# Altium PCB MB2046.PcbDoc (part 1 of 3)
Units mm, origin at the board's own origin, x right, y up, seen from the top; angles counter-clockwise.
Board outline 70 x 82.5 mm, 2 copper layers (Top Layer, Bottom Layer), stack 1.47 mm thick; 179 components, 148 nets, 719 pads, 862 vias.
Unrouted connection lines stored in the file: 135.
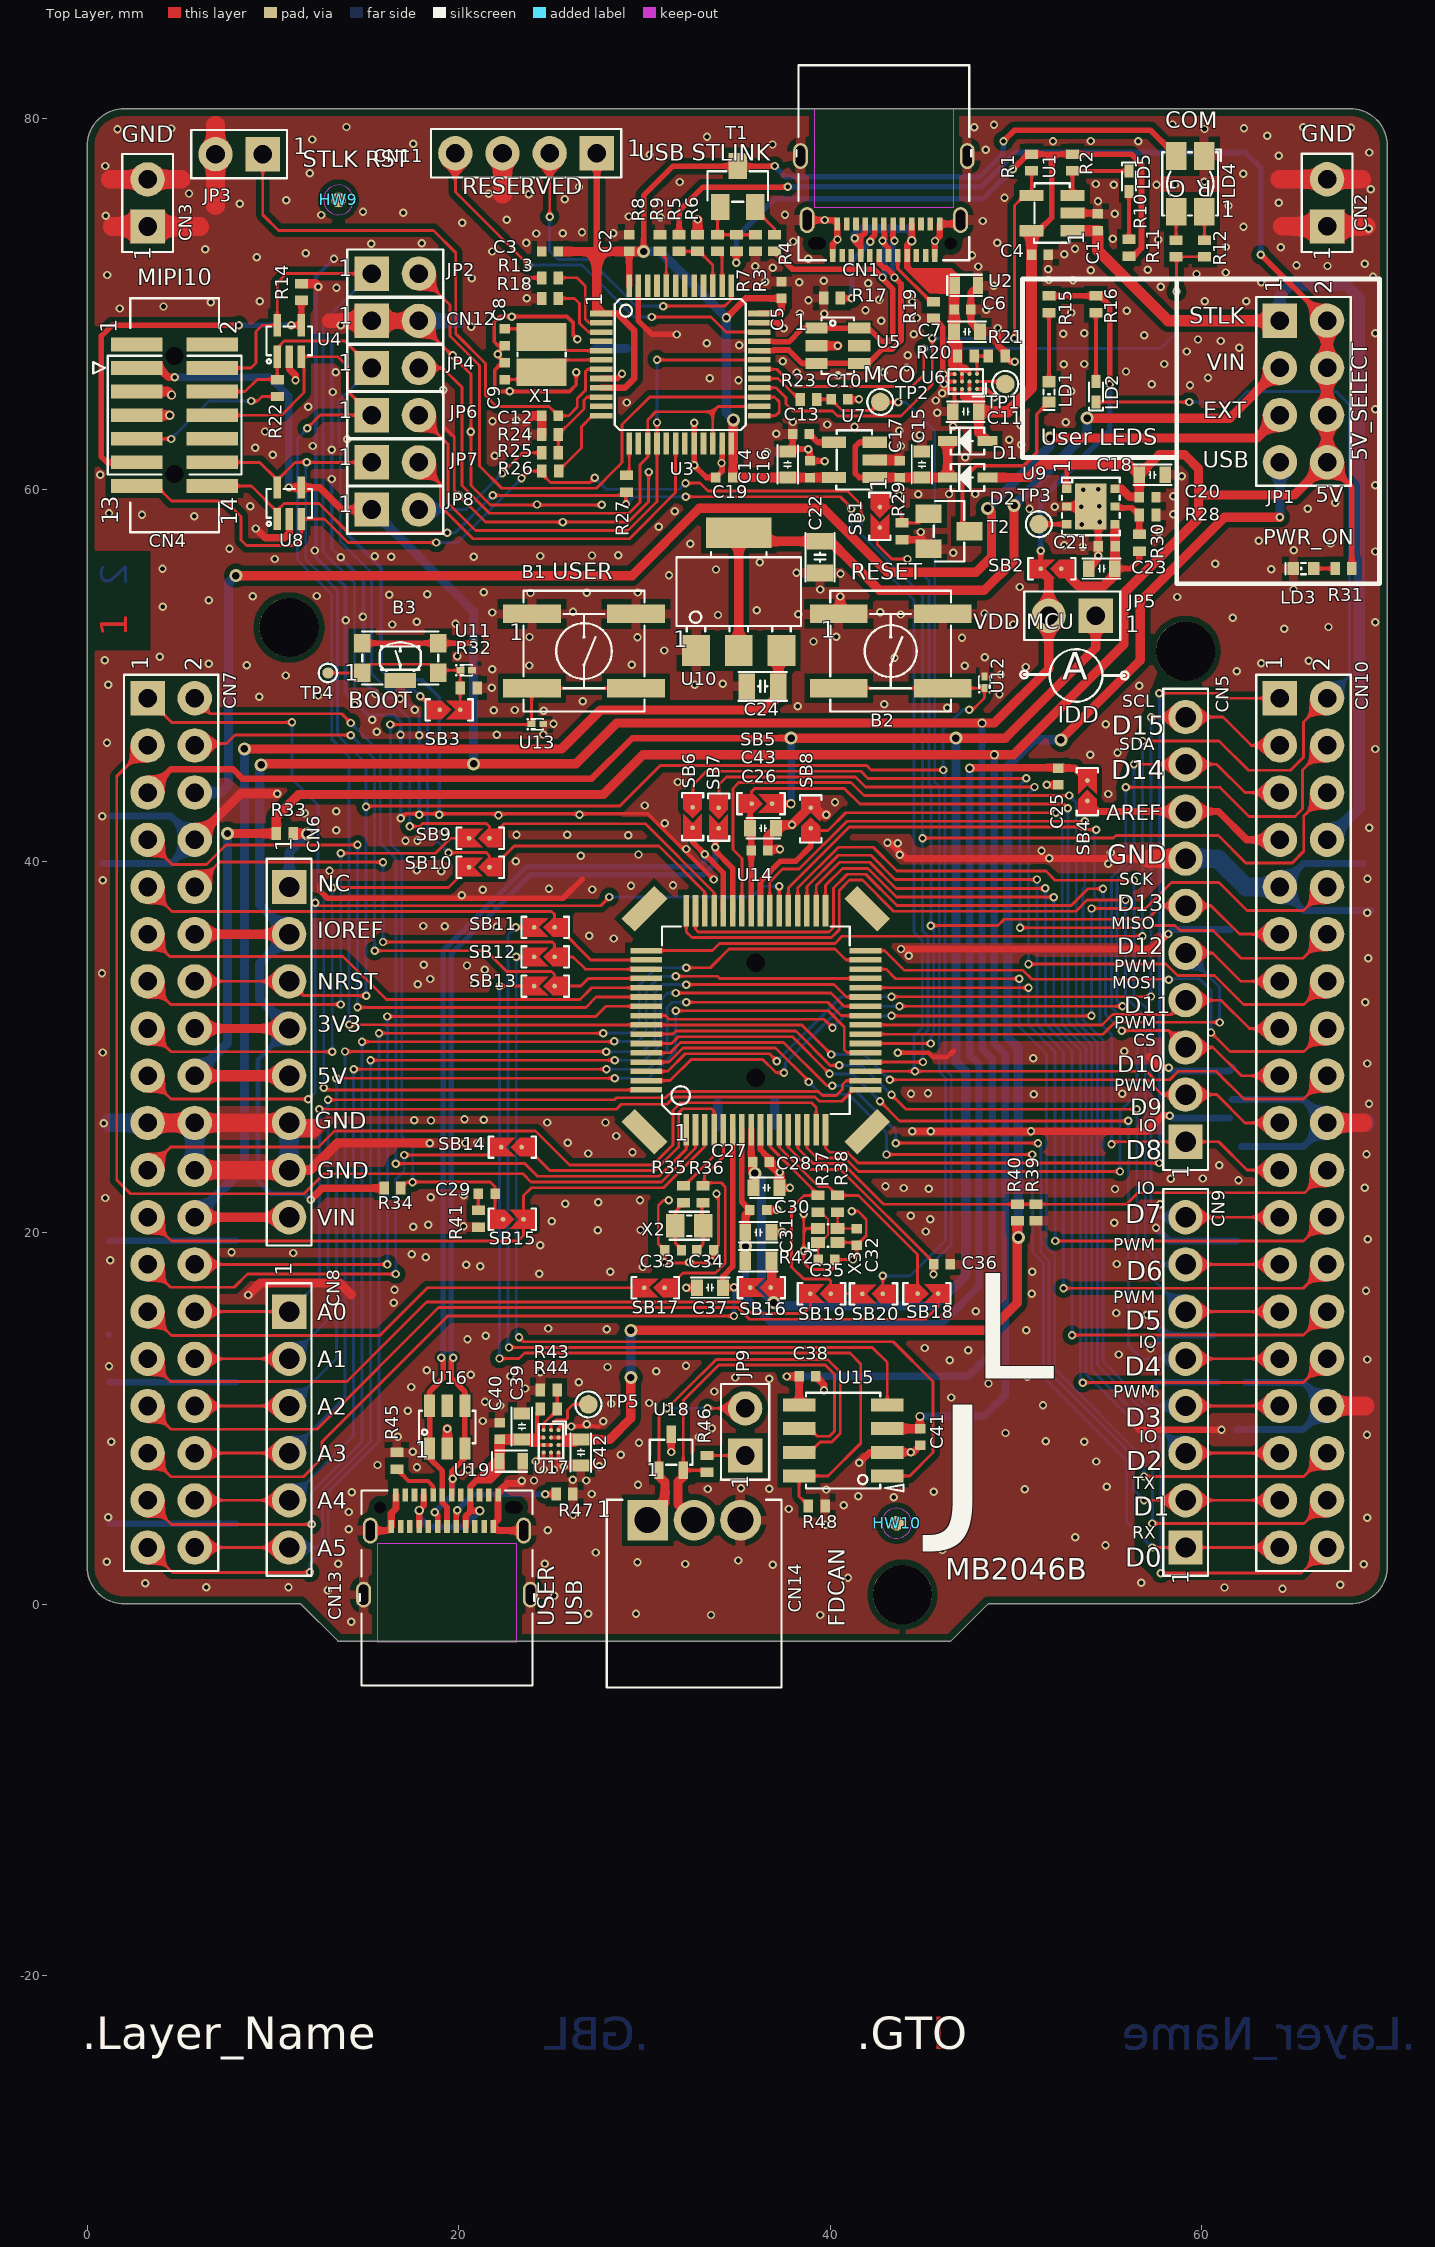
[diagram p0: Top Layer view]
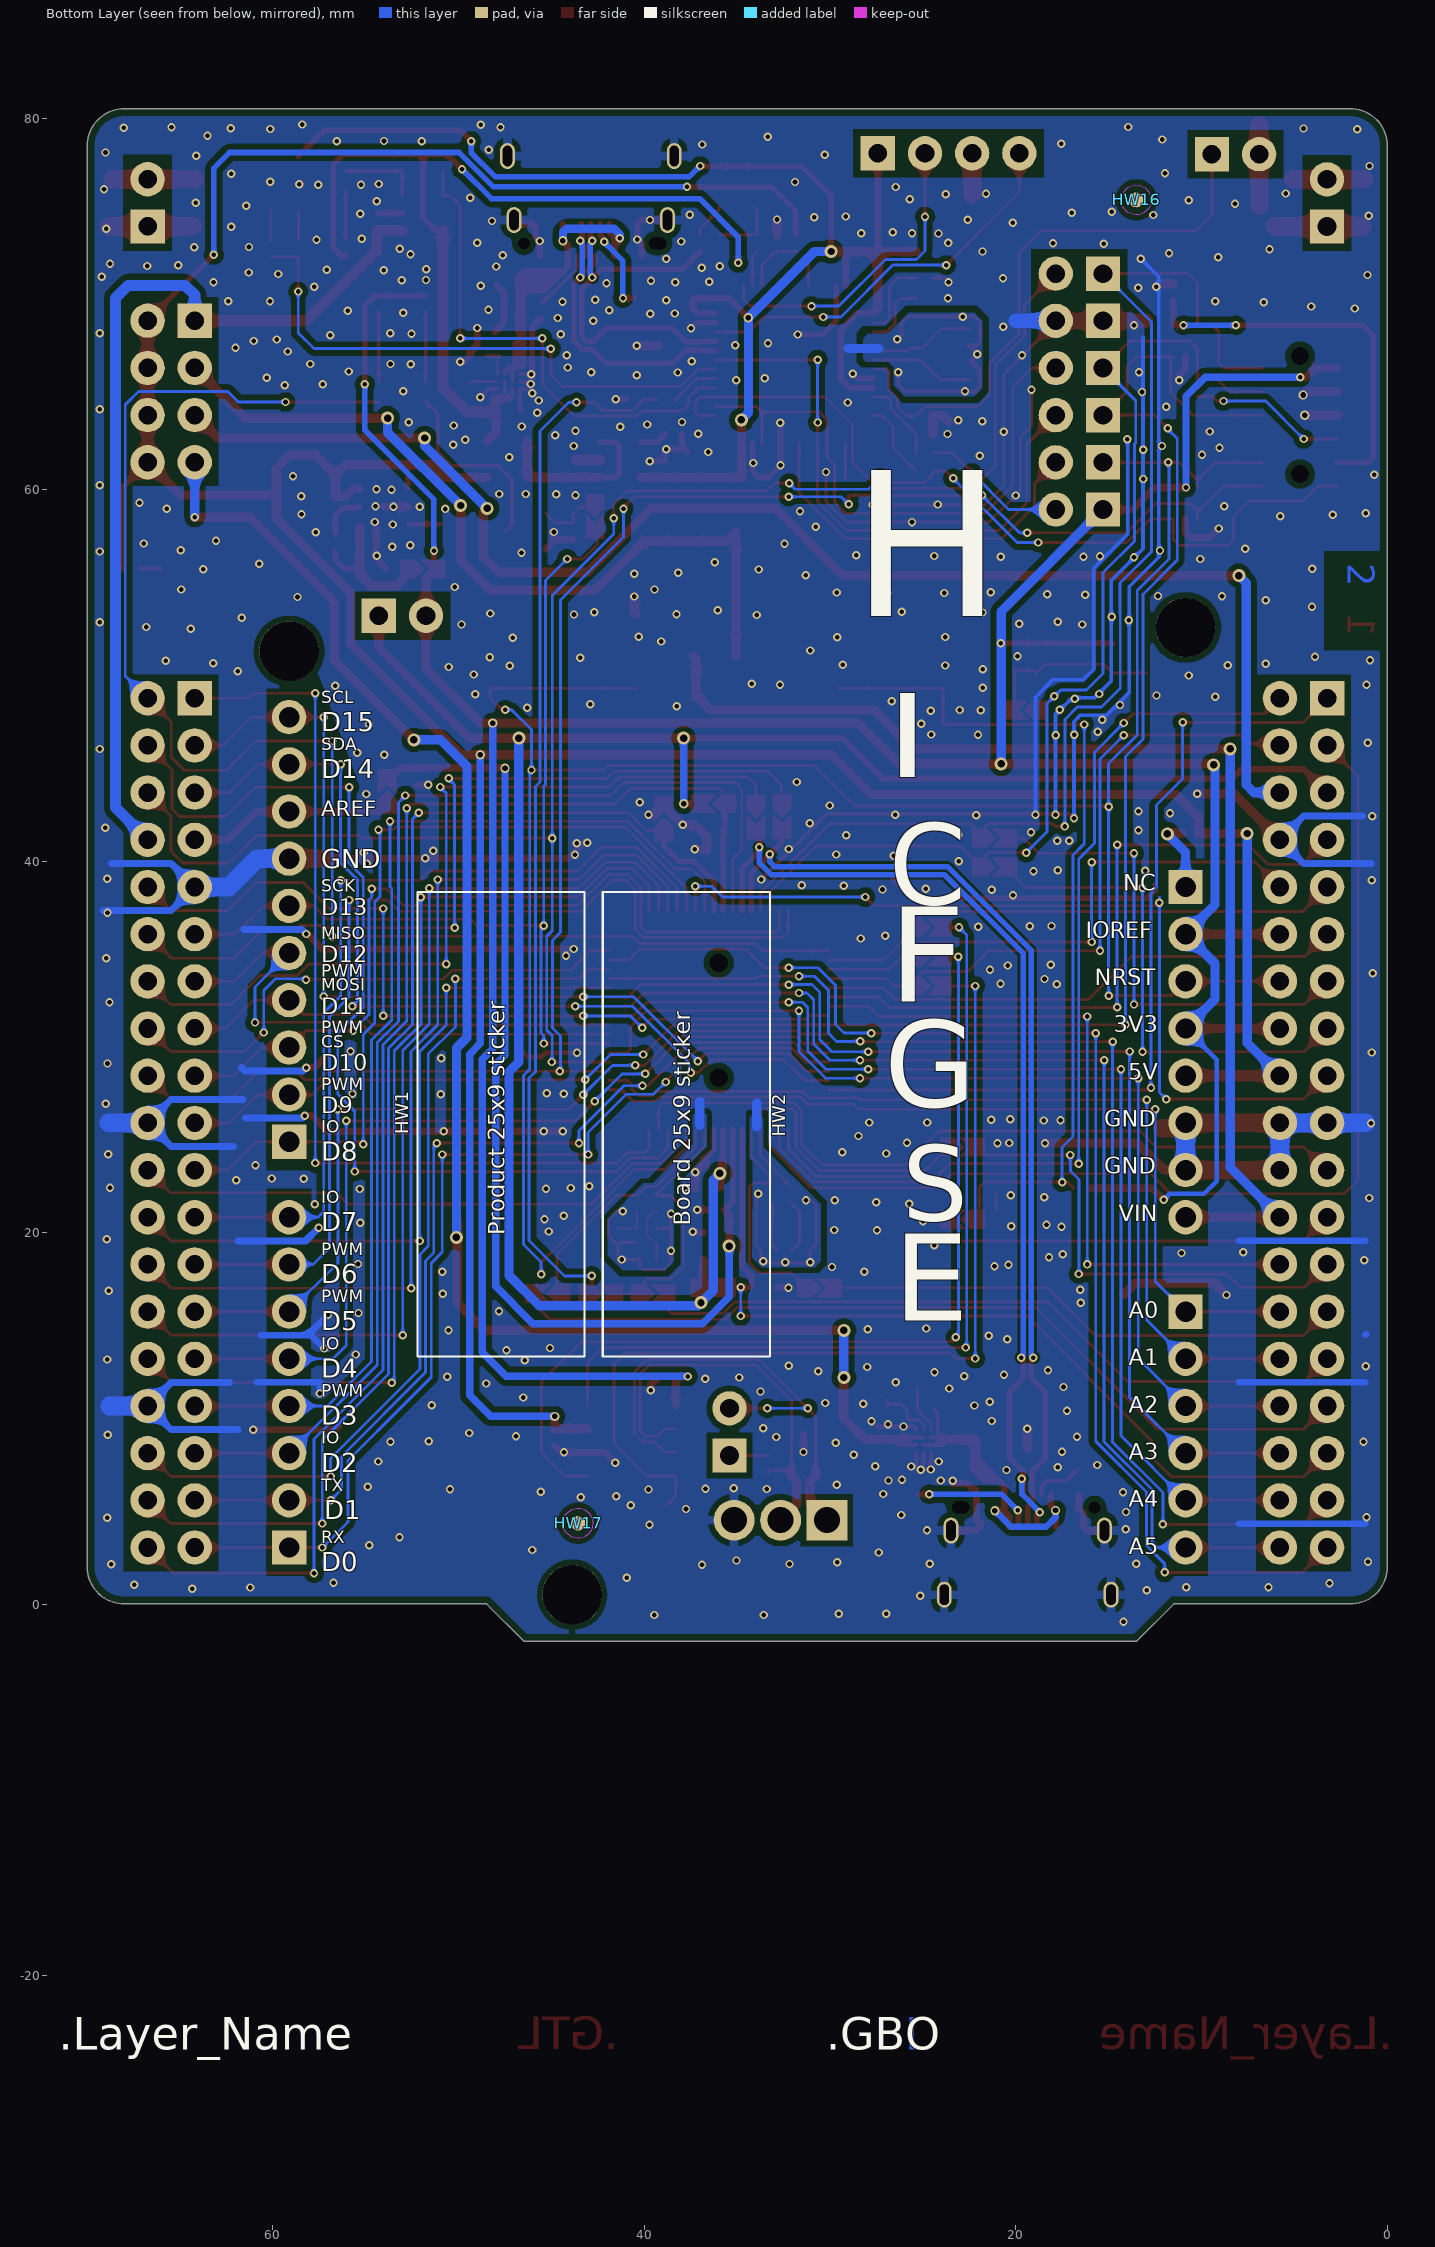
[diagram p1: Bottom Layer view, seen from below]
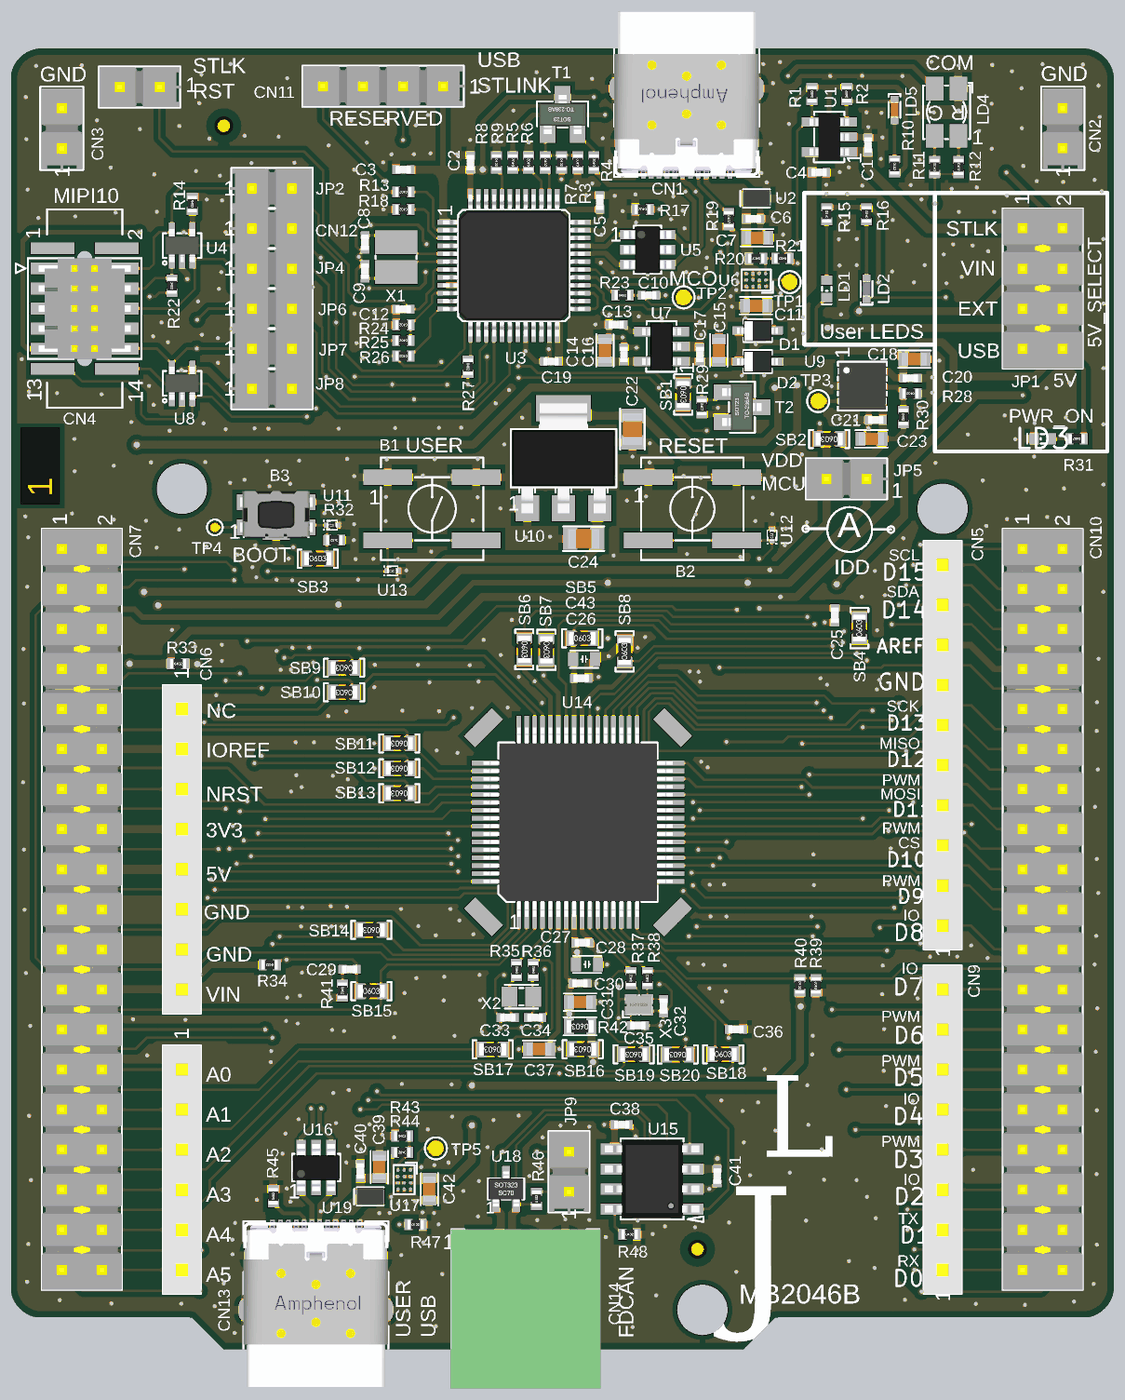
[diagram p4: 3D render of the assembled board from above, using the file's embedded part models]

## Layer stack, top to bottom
Top Solder: solder mask 0.015, Solder Resist, Dk 3.5
Top Layer: signal copper 0.035
Dielectric 1: core 1.4, Dk 4.2
Bottom Layer: signal copper 0.035
Bottom Solder: solder mask 0.015, Solder Resist, Dk 3.5

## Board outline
2.001,0.008 11.501,0.008 13.501,-1.992 46.501,-1.992 48.501,0.008 68.001,0.008 ccw(c68.001,2.008) 70.001,2.008 70.001,78.508 ccw(c68.001,78.508) 68.001,80.508 2.001,80.508 ccw(c2.001,78.508) 0.001,78.508 0.001,2.008 ccw(c2.001,2.008)

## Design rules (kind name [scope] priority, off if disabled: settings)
BoardOutlineClearance [All] p1: gap=0.4 ignorepadtopadclearanceinfootprint=FALSE
Clearance VIA&VIA [IsVia vs IsVia] p1: gap=0.152 ignorepadtopadclearanceinfootprint=TRUE except(0: Arc-Hole Track-Hole SMDPad-Hole THPad-Hole Via-Hole Fill-Hole Poly-Hole Region-Hole Text-Hole; 0.2: Via-Via)
Clearance STLK_USB [InDifferentialPair('STLK_USB')  OR InDifferentialPair('USB.D')] p2: gap=0.134 ignorepadtopadclearanceinfootprint=TRUE
Clearance X3 [(HasFootprint('CRY_NX1612SA_4P'))] p3: gap=0.1 ignorepadtopadclearanceinfootprint=TRUE
Clearance POLOGON [InPolygon] p4: gap=0.3 ignorepadtopadclearanceinfootprint=TRUE except(0: Arc-Hole Track-Hole SMDPad-Hole THPad-Hole Via-Hole Fill-Hole Poly-Hole Region-Hole Text-Hole)
Clearance SB [(HasFootprint('SOLDER-BRIDGE_R0603-0R'))] p5: gap=0.152 ignorepadtopadclearanceinfootprint=TRUE
Clearance [All] p6: gap=0.152 ignorepadtopadclearanceinfootprint=TRUE except(0: Arc-Hole Track-Hole SMDPad-Hole THPad-Hole Via-Hole Fill-Hole Poly-Hole Region-Hole Text-Hole; 0.15: THPad-Fill THPad-Poly THPad-Region; 0.2: SMDPad-SMDPad SMDPad-THPad THPad-THPad THPad-Via Via-Via)
ComponentClearance [All] p1 off: gap=0.025 collisioncheckmode=3 verticalgap=2540 showdistances=TRUE
DiffPairsRouting DiffPairsRouting_USB [InDifferentialPair('STLK_USB')OR InDifferentialPair('USB.D')] p1: maxlimit=0.134 minlimit=0.134 mostfreqgap=0.134 toplayer_minwidth=0.3 toplayer_maxwidth=0.3 toplayer_prefwidth=0.3 bottomlayer_minwidth=0.3 bottomlayer_maxwidth=0.3 bottomlayer_prefwidth=0.3 maxuncoupledlength=50
FanoutControl Fanout_BGA [IsBGA] p1: bgadir=Out bgaviamode=Closest fanoutstyle=Auto fanoutdirection=Alternating viagrid=0.025 // Fanout_BGA (Default Rule)
FanoutControl Fanout_LCC [IsLCC] p2: bgadir=Out bgaviamode=Closest fanoutstyle=Auto fanoutdirection=Alternating viagrid=0.025 // Fanout_LCC (Default Rule)
FanoutControl Fanout_SOIC [IsSOIC] p3: bgadir=Out bgaviamode=Closest fanoutstyle=Auto fanoutdirection=Alternating viagrid=0.025 // Fanout_SOIC (Default Rule)
FanoutControl Fanout_Small [(CompPinCount < 5)] p4: bgadir=Out bgaviamode=Closest fanoutstyle=Auto fanoutdirection=OutThenIn viagrid=0.025 // Fanout_Small (Default Rule)
FanoutControl Fanout_Default [All] p5: bgadir=Out bgaviamode=Closest fanoutstyle=Auto fanoutdirection=Alternating viagrid=0.025 // Fanout_Default (Default Rule)
Height [All] p1 off: minheight=0 maxheight=100 prefheight=0.5
HoleSize [All] p1: absolutevalues=TRUE maxlimit=10 minlimit=0.15 maxpercent=80.000 minpercent=20.000
HoleToHoleClearance [All] p1: gap=0.25 allowstackedmicrovias=TRUE
Length Length_USB [InNetClass('USB')] p1: maxlimit=50 minlimit=1
MatchedLengths [InDifferentialPairClass('DIFF_USB')] p1: tolerance=0.2 checknetsindiffpair=TRUE checkdiffpairvsdiffpair=FALSE checkxsignals=FALSE checkothers=FALSE
MaxMinImpedance "Schematic Impedance Constraint_3" [InNet('STLK_USB_P')] p1: minimum=85.00 maximum=95.00
MaxMinImpedance "Schematic Impedance Constraint_2" [InNet('USB.D_P')] p2: minimum=85.00 maximum=95.00
MaxMinImpedance "Schematic Impedance Constraint_1" [InNet('USB.D_N')] p3: minimum=85.00 maximum=95.00
MaxMinImpedance "Schematic Impedance Constraint" [InNet('STLK_USB_N')] p4: minimum=85.00 maximum=95.00
MinimumSolderMaskSliver [All] p1 off: minsoldermaskwidth=0.1
PlaneClearance [All] p1: clearance=0.6
PolygonConnect VIA [IsVia] p1: connectstyle=Direct reliefconductorwidth=0.254 reliefentries=4 polygonreliefangle="45 Angle" airgapwidth=0.254
PolygonConnect PolygonConnect_1 [All] p2: connectstyle=Relief reliefconductorwidth=0.5 reliefentries=4 polygonreliefangle="90 Angle" airgapwidth=0.3
RoutingVias [All] p1: holewidth=0.25 width=0.45 viastyle="Through Hole" minholewidth=0.25 minwidth=0.45 maxholewidth=0.5 maxwidth=0.7
SilkToSilkClearance [All] p1: silktosilkclearance=0
SilkToSolderMaskClearance [IsPad] p1: minsilkscreentomaskgap=0 clearancetoexposedcopper=TRUE
SolderMaskExpansion [All] p1: expansion=0.05 istentingtop=FALSE
Width Width_ALIM [InNetClass('ALIM')] p1: maxlimit=10 minlimit=0.12 preferedwidth=0.3
Width [All] p2: maxlimit=10 minlimit=0.1 preferedwidth=0.152 minimp=50.000000 maximp=50.000000 favimp=50.000000
16 further rules are at their usual default settings.

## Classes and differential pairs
component class U_TOP: HW9 HW10 HW16 HW17
component class Project_overview: HW1 HW2 HW5
net class PF[0..1]: PF0 PF1
net class PD[0..9]: PD0 PD1 PD2 PD3 PD4 PD5 PD6 PD7 PD8 PD9
component class U_USB-C_Device: C39 C40 C42 CN13 R39 R40 R43 R44 R45 R47 TP5 U16 U17 U19
component class U_FDCAN: C38 C41 CN14 HW15 JP9 R46 R48 U15 U18
component class U_Connectors: C25 CN5 CN6 CN7 CN8 CN9 CN10 R33 SB4 SB9 SB10 SB14 SB17 SB18 SB19
component class U_STM32_microcontroller_IOs: B1 B2 B3 C26 C27 C28 C29 C30 C31 C32 C33 C34 C35 C36 C37 C43 R32 R34 R35 R36 R37 R38 R41 R42 SB3 SB5 SB6 SB7 SB8 SB11 SB12 SB13 SB15 SB16 SB20 TP4 U11 U12 U13 U14 X2 X3
component class Power: C18 C20 C21 C22 C23 C24 CN2 CN3 HW5 HW6 JP1 JP5 LD1 LD2 LD3 R15 R16 R28 R29 R30 R31 SB1 SB2 T2 TP3 U9 U10
component class U_STLINK_V2EC: C1 C2 C3 C4 C5 C6 C7 C8 C9 C10 C11 C12 C13 C14 C15 C16 C17 C19 CN1 CN4 CN11 CN12 D1 D2 HW3 HW4 JP2 JP3 JP4 JP6 JP7 JP8 LD4 LD5 R1 R2 R3 R4 R5 R6 R7 R8 R9 R10 R11 R12 R13 R14 R17 R18 R19 R20 R21 R22 R23 R24 R25 R26 R27 T1 TP1 TP2 U1 U2 U3 U4 U5 U6 U7 U8 X1
net class PA[0..15]: PA0 PA1 PA2 PA3 PA4 PA5 PA6 PA7 PA8 PA9 PA10 PA11 PA12 PA13 PA14 PA15
net class PB[0..15]: PB0 PB1 PB2 PB3 PB4 PB5 PB6 PB7 PB8 PB9 PB10 PB11 PB12 PB13 PB14 PB15
net class PC[0..15]: PC0 PC1 PC2 PC3 PC4 PC5 PC6 PC7 PC8 PC9 PC10 PC11 PC12 PC13 PC14 PC15
differential pair USB.D: +USB.D_P -USB.D_N
differential pair STLK_USB: +STLK_USB_P -STLK_USB_N
differential pair CAN: +CAN_P -CAN_N

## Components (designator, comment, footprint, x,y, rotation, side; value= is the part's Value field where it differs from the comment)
B1 "SW_BLUE_KSC721JLFS" SWI_C&K_KSC721JLFS_BLUE 26.746,51.308 r0 top locked value=KSC721JLFS
B2 "SW_BLACK_KSC321JLFS" SWI_C&K_KSC321JLFS_BLACK 43.256,51.308 r0 top locked value=KSC321JLFS
B3 "SW-PUSH-CMS_KMR2_BLACK" SWI_C&K_Y78B23110FP__ITT_KMR231GLFS 16.855,50.933 r180 top locked value=KMR231GLFS
C1 "Capacitor" C0402 54.407,74.388 r270 top value=100nF
C2 "Capacitor" C0402 29.178,73.27 r90 top value=100nF
C3 "Capacitor" C0402 24.921,72.82 r180 top value=100nF
C4 "Capacitor" C0402 51.293,72.65 r180 top value=100nF
C5 "Capacitor" C0402 37.38,70.747 r90 top value=100nF
C6 "Capacitor" C0402 47.121,69.698 r0 top value=100pF
C7 "Capacitor" C0603 47.371,68.498 r0 top value=100nF
C8 "Capacitor" C0402 22.477,68.206 r90 top value=10pF
C9 "Capacitor" C0402 22.477,66.377 r90 top value=10pF
C10 "Capacitor" C0402 40.496,64.858 r180 top value=20pF
C11 "Capacitor" C0603 47.296,64.195 r0 top value=10uF
C12 "Capacitor" C0402 24.921,63.972 r0 top value=100nF
C13 "Capacitor" C0402 38.429,62.994 r0 top value=10nF
C14 "Capacitor" C0603 37.71,61.35 r270 top value=1uF
C15 "Capacitor" C0603 44.937,61.35 r270 top value=1uF
C16 "Capacitor" C0402 38.911,61.1 r270 top value=100nF
C17 "Capacitor" C0402 43.738,61.1 r270 top value=100nF
C18 "Capacitor" C0603 57.34,60.795 r180 top value=1uF
C19 "Capacitor" C0402 34.292,60.65 r180 top value=100nF
C20 "Capacitor" C0402 57.09,59.592 r180 top value=100nF
C21 "Capacitor" C0402 54.885,56.947 r0 top value=100nF
C22 "Capacitor" C0805 39.45,56.365 r90 top value=10uF
C23 "Capacitor" C0603 54.618,55.748 r0 top value=1uF
C24 "Capacitor" C0805 36.36,49.41 r0 top value=10uF
C25 "Capacitor" C0402 52.285,44.56 r270 top value=100nF
C26 "Capacitor" C0402 36.2,40.57 r180 top value=100nF
C27 "Capacitor" C0402 36.271,23.8 r180 top value=100nF
C28 "Capacitor" C0603_H0P8 36.576,22.416 r180 top value=4.7uF
C29 "Capacitor" C0402 21.508,22.1 r0 top value=100nF
C30 "Capacitor" C0402 36.13,21.216 r180 top value=100nF
C31 "Capacitor" C0603 36.13,20.016 r0 top value=1uF
C32 "Capacitor" C0402 41.424,19.77 r90 top value=6pF
C33 "Capacitor" C0402 31.545,19.05 r0 top value="7.5pF ± 0.1pF"
C34 "Capacitor" C0402 33.274,19.05 r180 top value="7.5pF ± 0.1pF"
C35 "Capacitor" C0402 39.8,18.55 r180 top value=6pF
C36 "Capacitor" C0402 46.025,18.293 r180 top value=100nF
C37 "Capacitor" C0603 33.525,17.043 r180 top value=1uF
C38 "Capacitor" C0402 38.776,12.258 r0 top value=100nF
C39 "Capacitor" C0603 23.4,9.565 r90 top value=100nF
C40 "Capacitor" C0402 22.2,9.315 r90 top value=100pF
C41 "Capacitor" C0402 44.843,8.992 r270 top value=100nF
C42 "Capacitor" C0603 26.575,8.165 r90 top value=10uF
C43 "Capacitor" C0603_H0P8 36.39,41.77 r180 top value=4.7uF
CN1 "USB_TYPE_C_Receptacle" CON_USB-TYPEC_AMPHENOL_12401826E412A 42.89,73.258 r180 top locked value=USB_C_12401826E412A
CN2 "Jumper_Header 2x1" CON_SAMTEC_TSW-102-09-X-S 66.751,75.438 r90 top locked value="Header 2x1"
CN3 "Jumper_Header 2x1" CON_SAMTEC_TSW-102-09-X-S 3.255,75.433 r90 top locked value="Header 2x1"
CN4 "Header 7x2" CON_STDC14_Receiver_MEDIUM_WITH_MIPI10_3D 4.704,64.007 r270 top locked value="Header 5x2"
CN5 "Socket 10x1" CON_SAMTEC_SSW-110-01-X-S 59.131,36.322 r90 top locked
CN6 "Socket 8x1" CON_SAMTEC_SSW-108-01-X-S 10.871,29.718 r270 top locked
CN7 "Header 19x2" CON_SAMTEC_TSW-119-09-X-D 4.521,25.908 r270 top locked
CN8 "Socket 6x1" CON_SAMTEC_SSW-106-01-X-S 10.871,9.398 r270 top locked
CN9 "Socket 8x1" CON_SAMTEC_SSW-108-01-X-S 59.131,11.938 r90 top locked
CN10 "Header 19x2" CON_SAMTEC_TSW-119-09-X-D 65.481,25.908 r270 top locked
CN11 "Header 4x1" CON_SAMTEC_TSW-104-07-G-S 23.63,78.108 r180 top locked
CN12 "Jumper_Header 2x1 Fitted" CON_SAMTEC_TSW-102-07-G-S 16.586,69.088 r0 top locked value="Header 2x1"
CN13 "USB_TYPE_C_Receptacle" CON_USB-TYPEC_AMPHENOL_12401826E412A 19.371,5.208 r0 top locked value=USB_C_12401826E412A
CN14 "Header 3x1" CON_WE-691382010003 32.675,4.518 r0 top locked
D1 "BAT60JFILM" DIO_SOD323 47.395,62.611 r180 top
D2 "BAT60JFILM" DIO_SOD323 47.395,60.65 r180 top
HW1 "STICKER_PRODUCT" STICKER_PRODUCT_25X9 47.727,25.832 r90 bottom locked value=N/A
HW2 "STICKER_BOARD" STICKER_BOARD_25X9 37.744,25.832 r90 bottom locked value=N/A
HW9 "FiducialPad" MIRE_PLACE_SMD_0P8MM 13.527,75.597 r90 top value="Fiducial Pad"
HW10 "FiducialPad" MIRE_PLACE_SMD_0P8MM 43.579,4.355 r90 top value="Fiducial Pad"
HW16 "FiducialPad" MIRE_PLACE_SMD_0P8MM 13.527,75.597 r90 bottom value="Fiducial Pad"
HW17 "FiducialPad" MIRE_PLACE_SMD_0P8MM 43.579,4.355 r90 bottom value="Fiducial Pad"
JP1 "Jumper_Header 4x2 Fitted 1-2" CON_SAMTEC_TSW-104-07-X-D 65.48,65.283 r270 top locked value="Header 4x2"
JP2 "Jumper_Header 2x1 Fitted" CON_SAMTEC_TSW-102-07-G-S 16.586,71.628 r0 top locked value="Header 2x1"
JP3 "Jumper_Header 2x1" CON_SAMTEC_TSW-102-07-G-S 8.18,78.058 r180 top locked value="Header 2x1"
JP4 "Jumper_Header 2x1 Fitted" CON_SAMTEC_TSW-102-07-G-S 16.586,66.548 r0 top locked value="Header 2x1"
JP5 "Jumper_Header 2x1 Fitted" CON_SAMTEC_TSW-102-07-G-S 53.03,53.208 r180 top locked value="Header 2x1"
JP6 "Jumper_Header 2x1 Fitted" CON_SAMTEC_TSW-102-07-G-S 16.586,64.008 r0 top locked value="Header 2x1"
JP7 "Jumper_Header 2x1 Fitted" CON_SAMTEC_TSW-102-07-G-S 16.586,61.468 r0 top locked value="Header 2x1"
JP8 "Jumper_Header 2x1 Fitted" CON_SAMTEC_TSW-102-07-G-S 16.586,58.928 r0 top locked value="Header 2x1"
JP9 "Jumper_Header 2x1" CON_SAMTEC_TSW-102-07-G-S 35.425,9.271 r90 top value="Header 2x1"
LD1 "LED_green" "LED_0402_EVERLIGHT_16-213SYGC/S530-E3-TR8 _YELLOW-GREEN_1A2K_H0P45" 51.78,65.258 r90 top locked value=Yellow/Green
LD2 "LED_blue" LED_0402_KINGBRIGHT_KPHHS-1005QBC-D-V_BLUE_1A2K_H0P5 54.305,65.258 r270 top locked value=Blue
LD3 "LED_green" "LED_0402_EVERLIGHT_16-213SYGC/S530-E3-TR8 _YELLOW-GREEN_1A2K_H0P45" 65.48,55.748 r0 top locked value=Yellow/Green
LD4 "LED_BICOLOR" LED_BI-GR_WE-150141SV73110 59.38,76.458 r180 top locked value=Red/Green
LD5 "LED_red" LED_0402_KINGBRIGHT_KPHHS-1005SURCK_HYPER-RED_1A2K_H0P5 56.083,76.606 r90 top locked value=Red
R1 "Resistor" R0402 50.843,77.606 r90 top value=100K
R2 "Resistor" R0402 53.043,77.606 r90 top value=100K
R3 "Resistor" R0402 35.983,73.271 r90 top value=36K
R4 "Resistor" R0402 37.008,73.271 r90 top value=1K5
R5 "Resistor" R0402 32.863,73.271 r90 top value=10K
R6 "Resistor" R0402 33.934,73.271 r270 top value=100R
R7 "Resistor" R0402 34.959,73.271 r270 top value=10K
R8 "Resistor" R0402 30.828,73.27 r270 top value=100K
R9 "Resistor" R0402 31.863,73.27 r90 top value=5K1
R10 "Resistor" R0402 56.083,73.025 r270 top value=1K
R11 "Resistor" R0402 58.623,72.983 r90 top locked value=330R
R12 "Resistor" R0402 60.147,72.983 r270 top locked value=1K
R13 "Resistor" R0402 24.921,71.403 r180 top value=10K
R14 "Resistor" R0402 11.532,70.637 r270 top value=100R
R15 "Resistor" R0402 51.78,69.983 r90 top value=680R
R16 "Resistor" R0402 54.305,69.983 r90 top value=360R
R17 "Resistor" R0402 40.097,70.303 r180 top value=5K1
R18 "Resistor" R0402 24.921,70.293 r180 top value=10K
R19 "Resistor" R0402 45.564,69.672 r270 top value=5K1
R20 "Resistor" R0402 47.304,67.188 r180 top value=680K
R21 "Resistor" R0402 48.967,67.188 r180 top value=180K
R22 "Resistor" R0402 10.236,65.463 r270 top value=0R
R23 "Resistor" R0402 38.827,64.858 r0 top value=100R
R24 "Resistor" R0402 24.921,62.972 r180 top value=10K
R25 "Resistor" R0402 24.921,61.984 r180 top value=10K
R26 "Resistor" R0402 24.925,60.998 r180 top value=33R
R27 "Resistor" R0402 29.025,60.315 r270 top value=0R
R28 "Resistor" R0402 57.09,58.623 r180 top value=15K
R29 "Resistor" R0402 43.855,57.76 r270 top value=1M
R30 "Resistor" R0402 56.64,57.135 r270 top value=47K
R31 "Resistor" R0402 67.633,55.753 r180 top value=680R
R32 "Resistor" R0402 20.538,49.322 r180 top value=10K
R33 "Resistor" R0402 10.633,41.485 r0 top value=1K
R34 "Resistor" R0402 16.44,22.393 r180 top value=5K1
R35 "Resistor" R0402 32.1,22.065 r90 top value=0R
R36 "Resistor" R0402 33.165,22.065 r90 top value=0R
R37 "Resistor" R0402 39.35,21.552 r90 top value=0R
R38 "Resistor" R0402 40.4,21.552 r90 top value=0R
R39 "Resistor" R0402 51.09,21.085 r90 top value=82K
R40 "Resistor" R0402 50.074,21.085 r270 top value=33K
R41 "Resistor" R0402 21.057,20.75 r270 top value=100R
R42 "Resistor" R0603 36.13,18.489 r180 top value=0R
R43 "Resistor" R0402 24.848,11.533 r0 top value=180K
R44 "Resistor" R0402 24.848,10.492 r180 top value=680K
R45 "Resistor" R0402 16.669,7.714 r90 top value=5K1
R46 "Resistor" R0402 33.368,7.551 r90 top value=120R
R47 "Resistor" R0402 25.698,5.918 r0 top value=5K1
R48 "Resistor" R0402 39.275,5.295 r0 top value=10K
SB1 "SB_ON" SOLDER-BRIDGE_R0603-0R 42.673,58.56 r270 top value=0R
SB2 "SB_ON" SOLDER-BRIDGE_R0603-0R 51.935,55.738 r180 top value=0R
SB3 "SB_ON" SOLDER-BRIDGE_R0603-0R 19.488,48.145 r0 top value=0R
SB4 "SB_ON" SOLDER-BRIDGE_R0603-0R 53.847,43.74 r90 top value=0R
SB5 "SB_ON" SOLDER-BRIDGE_R0603-0R 36.273,43.095 r0 top value=0R
SB6 "SB_ON" SOLDER-BRIDGE_R0603-0R 32.595,42.395 r270 top value=0R
SB7 "SB_ON" SOLDER-BRIDGE_R0603-0R 33.992,42.365 r270 top value=0R
SB8 "SB_ON" SOLDER-BRIDGE_R0603-0R 38.955,42.27 r90 top value=0R
SB9 "SB_ON" SOLDER-BRIDGE_R0603-0R 21.158,41.234 r180 top value=0R
SB10 "SB_ON" SOLDER-BRIDGE_R0603-0R 21.157,39.672 r180 top value=0R
SB11 "SB_ON" SOLDER-BRIDGE_R0603-0R 24.663,36.436 r180 top value=0R
SB12 "SB_ON" SOLDER-BRIDGE_R0603-0R 24.663,34.846 r180 top value=0R
SB13 "SB_ON" SOLDER-BRIDGE_R0603-0R 24.663,33.274 r180 top value=0R
SB14 "SB_ON" SOLDER-BRIDGE_R0603-0R 22.89,24.605 r180 top value=0R
SB15 "SB_ON" SOLDER-BRIDGE_R0603-0R 22.89,20.72 r0 top value=0R
SB16 "SB_ON" SOLDER-BRIDGE_R0603-0R 36.297,17.043 r180 top value=0R
SB17 "SB_ON" SOLDER-BRIDGE_R0603-0R 30.583,17.03 r180 top value=0R
SB18 "SB_ON" SOLDER-BRIDGE_R0603-0R 45.207,16.718 r0 top value=0R
SB19 "SB_ON" SOLDER-BRIDGE_R0603-0R 39.533,16.712 r180 top value=0R
SB20 "SB_ON" SOLDER-BRIDGE_R0603-0R 42.33,16.705 r180 top value=0R
T1 "9013-SOT23" NPN_SOT23 35.027,76.319 r0 top value=BSR14
T2 "BSN20" MOS_SOT23 46.395,57.76 r270 top value=BSN20BK
TP1 "Test Point" TP_SMD_1MM 49.427,65.686 r90 top value=N/A
TP2 "Test Point" TP_SMD_1MM 42.697,64.719 r90 top value=N/A
TP3 "Test Point" TP_SMD_1MM 51.235,58.14 r180 top value=N/A
TP4 "Test Point" TP_SMD_0-6MM 12.96,50.13 r90 top value=N/A
TP5 "Test Point" TP_SMD_1MM 26.982,10.753 r90 top value=N/A
U1 "STMPS2141STR" MOS_SOT23-5L 51.943,74.888 r90 top
U2 "ESD-TRANSIL" ESD_QFN1610_2N_1K_2A 47.326,70.992 r0 top value=ESDA25P35-1U1M
U3 "STLINK-V2EC" ICC_LQFP48_7X7_P050 31.928,66.732 r270 top locked
U4 "ESDALC6V1W5" ESD_SOT323-5L 10.882,68.003 r0 top
U5 "USBLC6-2SC6" ESD_SOT23-6L 40.411,67.742 r270 top
U6 "FPF3380UCX" ICC_WLCSP12_1P858x1P318_P040 47.301,65.818 r180 top
U7 "LDK120M33R" REG_SOT23-5L 41.299,61.6 r90 top
U8 "ESDALC6V1W5" ESD_SOT323-5L 10.882,59.265 r0 top
U9 "LD39100PUR" ICC_DFN6-EPAD_3X3_P095 54.036,59.09 r270 top
U10 "LD1117S50TR" REG_SOT223-TAB 35.077,54.51 r0 top
U11 "ESD-TRANSIL" ESD_ST0201 20.4,50.273 r0 top value=ESDALC6V1-1U2
U12 "ESD-TRANSIL" ESD_ST0201 48.305,49.622 r90 top value=ESDALC6V1-1U2
U13 "ESD-TRANSIL" ESD_ST0201 24.237,47.373 r0 top value=ESDALC6V1-1U2
U14 "STM32C071RB" ICC_LQFP64_10X10_P050_SOCKET_YAMAICHI_IC149-064-069-B5_NM 35.999,31.433 r0 top locked value=STM32C071RBT6
U15 "MCP2562FD" ICC_SO8_5X4_P127 40.701,8.807 r90 top value=MCP2562FDT-H/SN
U16 "USBLC6-2SC6" ESD_SOT23-6L 19.387,9.532 r0 top
U17 "AW329xxFCR" ICC_WLCSP12_1P858x1P318_P040 24.975,8.766 r270 top value=FPF3380UCX
U18 "ESD-TRANSIL-DUAL-BIDIR" DIO_SOT323 31.437,8.179 r0 top value=ESDCAN03-2BWY
U19 "ESD-TRANSIL" ESD_QFN1610_2N_1K_2A 22.825,7.696 r0 top value=ESDA25P35-1U1M
X1 "XTAL_2_PINS" CRY_NX3225GD_2P 24.46,67.266 r90 top value=8MHz
X2 "XTAL_2_PINS" CRY_NX2012SA_2P 32.41,20.369 r180 top value=32.768KHz
X3 "XTAL_4_PINS" CRY_NX1612SA_4P 39.875,19.845 r0 top value=48MHz

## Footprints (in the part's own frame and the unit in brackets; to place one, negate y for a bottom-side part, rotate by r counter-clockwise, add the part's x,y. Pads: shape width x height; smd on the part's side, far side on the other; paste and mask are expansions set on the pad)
C0402 [mm]
  rect 0.51x0.56 smd mask+0.05: 1(-0.45,0) 2(0.45,0)
  body extent -0.5,-0.3 0.5,0.3, height 0.4
C0603 [mm]
  rect 0.64x0.89 smd mask+0.05: 1(-0.7,0) 2(0.7,0)
  silkscreen extent -1.05,-0.55 1.02,0.55, body extent -0.9,-0.5 0.9,0.5, height 1.4
C0603_H0P8 [mm] "MCD-01540"
  rect 0.64x0.89 smd mask+0.05: 1(-0.7,0) 2(0.7,0)
  silkscreen extent -0.9,-0.55 0.9,0.55, body extent -0.9,-0.5 0.9,0.5, height 1
C0805 [mm]
  rect 0.9x1.4 smd mask+0.05: 1(-0.85,0) 2(0.85,0)
  silkscreen extent -1.3,-0.77 1.3,0.77, body extent -1.1,-0.7 1.1,0.7, height 1.35
CON_SAMTEC_SSW-106-01-X-S [mm] "MCD-02079"
  rect 1.85x1.85 / inner round 1.85 / far side rect 1.85x1.85 hole 1.1 mask+0.05: 1(-6.35,0)
  round 1.85 hole 1.1 mask+0.05: 2(-3.81,0) 3(-1.27,0) 4(1.27,0) 5(3.81,0) 6(6.35,0)
  silkscreen extent -7.88,-1.2 7.88,1.2, body extent -7.88,-1.21 7.88,1.21, height 8.51
CON_SAMTEC_SSW-108-01-X-S [mm] "MCD-01743"
  rect 1.85x1.85 / inner round 1.85 / far side rect 1.85x1.85 hole 1.1 mask+0.05: 1(-8.89,0)
  round 1.85 hole 1.1 mask+0.05: 2(-6.35,0) 3(-3.81,0) 4(-1.27,0) 5(1.27,0) 6(3.81,0) 7(6.35,0) 8(8.89,0)
  silkscreen extent -10.42,-1.2 10.42,1.2, body extent -10.42,-1.21 10.42,1.21, height 8.51
CON_SAMTEC_SSW-110-01-X-S [mm] "MCD-02080"
  rect 1.85x1.85 / inner round 1.85 / far side rect 1.85x1.85 hole 1.1 mask+0.05: 1(-11.43,0)
  round 1.85 hole 1.1 mask+0.05: 2(-8.89,0) 3(-6.35,0) 4(-3.81,0) 5(-1.27,0) 6(1.27,0) 7(3.81,0) 8(6.35,0) 9(8.89,0) 10(11.43,0)
  silkscreen extent -12.96,-1.2 12.96,1.2, body extent -12.96,-1.21 12.96,1.21, height 8.51
CON_SAMTEC_TSW-102-07-G-S [mm]
  rect 1.85x1.85 / inner round 1.85 / far side rect 1.85x1.85 hole 1 mask+0.05: 1(-1.27,0)
  round 1.85 hole 1 mask+0.05: 2(1.27,0)
  silkscreen extent -2.58,-1.3 2.58,1.3, body extent -2.67,-1.3 2.58,1.3, height 8.38
CON_SAMTEC_TSW-102-09-X-S [mm]
  rect 1.85x1.85 / inner round 1.85 / far side rect 1.85x1.85 hole 1 mask+0.05: 1(-1.27,0)
  round 1.85 hole 1 mask+0.05: 2(1.27,0)
  silkscreen extent -2.64,-1.37 2.64,1.37, body extent -2.67,-1.3 2.58,1.3, height 8.38
CON_SAMTEC_TSW-104-07-G-S [mm]
  rect 1.85x1.85 / inner round 1.85 / far side rect 1.85x1.85 hole 1 mask+0.05: 1(-3.81,0)
  round 1.85 hole 1 mask+0.05: 2(-1.27,0) 3(1.27,0) 4(3.81,0)
  silkscreen extent -5.12,-1.3 5.12,1.3, body extent -5.21,-1.37 5.18,1.37, height 8.38
CON_SAMTEC_TSW-104-07-X-D [mm]
  rect 1.85x1.85 / inner round 1.85 / far side rect 1.85x1.85 hole 1 mask+0.05: 1(-3.81,-1.27)
  round 1.85 hole 1 mask+0.05: 2(-3.81,1.27) 3(-1.27,-1.27) 4(-1.27,1.27) 5(1.27,-1.27) 6(1.27,1.27) 7(3.81,-1.27) 8(3.81,1.27)
  silkscreen extent -5.08,-2.54 5.08,2.54, body extent -5.08,-2.54 5.08,2.54, height 8.38
CON_SAMTEC_TSW-119-09-X-D [mm]
  rect 1.85x1.85 / inner round 1.85 / far side rect 1.85x1.85 hole 1 mask+0.05: 1(-22.86,-1.27)
  round 1.85 hole 1 mask+0.05: 2(-22.86,1.27) 3(-20.32,-1.27) 4(-20.32,1.27) 5(-17.78,-1.27) 6(-17.78,1.27) 7(-15.24,-1.27) 8(-15.24,1.27) 9(-12.7,-1.27) 10(-12.7,1.27) 11(-10.16,-1.27) 12(-10.16,1.27) 13(-7.62,-1.27) 14(-7.62,1.27) 15(-5.08,-1.27) 16(-5.08,1.27) 17(-2.54,-1.27) 18(-2.54,1.27) 19(0,-1.27) 20(0,1.27) 21(2.54,-1.27) 22(2.54,1.27) 23(5.08,-1.27) 24(5.08,1.27) 25(7.62,-1.27) 26(7.62,1.27) 27(10.16,-1.27) 28(10.16,1.27) 29(12.7,-1.27) 30(12.7,1.27) 31(15.24,-1.27) 32(15.24,1.27) 33(17.78,-1.27) 34(17.78,1.27) 35(20.32,-1.27) 36(20.32,1.27) 37(22.86,-1.27) 38(22.86,1.27)
  silkscreen extent -24.13,-2.54 24.13,2.54, body extent -24.13,-2.55 24.13,2.54, height 8.38
CON_STDC14_Receiver_MEDIUM_WITH_MIPI10_3D [mm] "compatible with FTSH-105-01-L-DV,-K and FTSH-107-01-L-DV,-K,-A,-P,-ES"
  round 0 all layers, no hole mask+0: 0(-5.445,0) 0(5.445,0)
  round 0 hole 0.97 unplated mask+0.038: 0(-3.175,0) 0(3.175,0)
  rect 0.74x2.79 smd mask+0.05: 1(-3.81,-2.032) 2(-3.81,2.032) 3(-2.54,-2.032) 4(-2.54,2.032) 5(-1.27,-2.032) 6(-1.27,2.032) 7(0,-2.032) 8(0,2.032) 9(1.27,-2.032) 10(1.27,2.032) 11(2.54,-2.032) 12(2.54,2.032) 13(3.81,-2.032) 14(3.81,2.032)
  silkscreen extent -6.3,-4.38 6.3,3.6, body extent -6.3,-2.92 6.3,2.92, height 6.6
CON_USB-TYPEC_AMPHENOL_12401826E412A [mm] "MCD-03232"
  round 0 hole 0.65 unplated mask+0.05: 0(-3.6,0)
  round 0 hole 0.65 slot 0.95 at 0 deg unplated mask+0.05: 0(3.6,0)
  rect 0.3x0.7 smd mask+0.05: A1(-2.75,0.66) A2(-2.25,0.66) A3(-1.75,0.66) A4(-1.25,0.66) A5(-0.75,0.66) A6(-0.25,0.66) A7(0.25,0.66) A8(0.75,0.66) A9(1.25,0.66) A10(1.75,0.66) A11(2.25,0.66) A12(2.75,0.66) B1(2.5,-1.04) B2(2,-1.04) B3(1.5,-1.04) B4(1,-1.04) B5(0.5,-1.04) B6(0,-1.04) B7(-0.5,-1.04) B8(-1,-1.04) B9(-1.5,-1.04) B10(-2,-1.04) B11(-2.5,-1.04) B12(-3,-1.04)
  oval 0.8x1.4 hole 0.5 slot 1.1 at 90 deg mask+0.05: SH1(-4.13,-1.25) SH2(4.13,-1.25) SH3(-4.49,-4.7) SH4(4.49,-4.7)
  Top Layer keep-out region: -3.75,-7.24 3.75,-7.24 3.75,-1.95 -3.75,-1.95
  silkscreen extent -4.7,-9.59 4.7,0.91, body extent -4.6,-9.59 4.6,0.91, height 3.26
CON_WE-691382010003 [mm]
  rect 2.2x2.2 hole 1.4 mask+0.05: 1(-2.5,0)
  round 2.2 hole 1.4 mask+0.05: 2(0,0) 3(2.5,0)
  silkscreen extent -4.7,-9 4.7,1.1, body extent -4.75,-9 4.75,1.1, height 8.15
CRY_NX1612SA_4P [mm] "MCD-02262"
  rect 0.75x0.6 smd mask+0.038: 1(-0.525,-0.375) 2(0.525,-0.375) 3(0.525,0.375) 4(-0.525,0.375)
  silkscreen extent -1.02,-0.8 0.03,0.6, body extent -0.8,-0.6 0.8,0.6, height 0.51
CRY_NX2012SA_2P [mm]
  rect 1x1.25 smd mask+0.05: 1(-0.75,0) 2(0.75,0)
  silkscreen extent -1.05,-0.75 1.05,0.75, body extent -1.05,-0.63 1.05,0.63, height 0.6
CRY_NX3225GD_2P [mm]
  rect 1.5x2.7 smd mask+0.05: 1(-0.95,0) 2(0.95,0)
  silkscreen extent -0.1,-1.3 0.1,1.3, body extent -1.65,-1.31 1.65,1.3, height 1
DIO_SOD323 [mm]
  rect 1.06x0.54 smd mask+0.05: 1(-1.07,0) 2(1.07,0)
  silkscreen extent -0.9,-0.73 0.9,0.73, body extent -1.3,-0.78 1.3,0.78, height 1.17
DIO_SOT323 [mm]
  rect 0.5x0.95 smd mask+0.05: 1(-0.65,-0.975) 2(0.65,-0.975) 3(0,0.975)
  silkscreen extent -1.15,-0.67 1.15,0.67, body extent -1.15,-1.12 1.15,1.12, height 1.1
ESD_QFN1610_2N_1K_2A [mm] "DFN, 2-Leads, Body 1.60x1.00mm"
  rect 0.55x0.9 smd mask+0.05: 1(-0.625,0) 2(0.625,0)
  silkscreen extent -1.02,-0.58 0.85,0.58, body extent -0.85,-0.55 0.85,0.55, height 0.6
ESD_SOT23-6L [mm]
  rect 0.6x1.2 smd mask+0.05: 1(-0.95,-1.15) 2(0,-1.15) 3(0.95,-1.15) 4(0.95,1.15) 5(0,1.15) 6(-0.95,1.15)
  silkscreen extent -1.53,-0.87 1.53,0.87, body extent -1.52,-1.5 1.52,1.5, height 1.45
ESD_SOT323-5L [mm]
  rect 0.4x1.2 smd mask+0.05: 1(-0.65,-0.85) 2(0,-0.85) 3(0.65,-0.85) 4(0.65,0.85) 5(-0.65,0.85)
  silkscreen extent -1.23,-1.21 1.23,0.77, body extent -1.15,-1.05 1.15,1.05, height 1.1
ESD_ST0201 [mm]
  rect 0.425x0.33 smd mask+0.05: 1(-0.312,0) 2(0.312,0)
  silkscreen extent -0.55,-0.3 0.33,0.3, body extent -0.34,-0.18 0.34,0.18, height 0.34
ICC_DFN6-EPAD_3X3_P095 [mm]
  rect 0.45x0.5 smd mask+0.05: 1(-0.95,-1.3) 2(0,-1.3) 3(0.95,-1.3) 4(0.95,1.3) 5(0,1.3) 6(-0.95,1.3)
  rect 2.5x1.7 smd mask+0.05: EP(0,0)
  silkscreen extent -1.55,-1.55 1.55,1.55, body extent -1.55,-1.55 1.55,1.55, height 1
ICC_LQFP48_7X7_P050 [mm]
  rect 0.3x1.2 smd mask+0.05: 1(-2.75,-4.25) 2(-2.25,-4.25) 3(-1.75,-4.25) 4(-1.25,-4.25) 5(-0.75,-4.25) 6(-0.25,-4.25) 7(0.25,-4.25) 8(0.75,-4.25) 9(1.25,-4.25) 10(1.75,-4.25) 11(2.25,-4.25) 12(2.75,-4.25) 25(2.75,4.25) 26(2.25,4.25) 27(1.75,4.25) 28(1.25,4.25) 29(0.75,4.25) 30(0.25,4.25) 31(-0.25,4.25) 32(-0.75,4.25) 33(-1.25,4.25) 34(-1.75,4.25) 35(-2.25,4.25) 36(-2.75,4.25)
  rect 1.2x0.3 smd mask+0.05: 13(4.25,-2.75) 14(4.25,-2.25) 15(4.25,-1.75) 16(4.25,-1.25) 17(4.25,-0.75) 18(4.25,-0.25) 19(4.25,0.25) 20(4.25,0.75) 21(4.25,1.25) 22(4.25,1.75) 23(4.25,2.25) 24(4.25,2.75) 37(-4.25,2.75) 38(-4.25,2.25) 39(-4.25,1.75) 40(-4.25,1.25) 41(-4.25,0.75) 42(-4.25,0.25) 43(-4.25,-0.25) 44(-4.25,-0.75) 45(-4.25,-1.25) 46(-4.25,-1.75) 47(-4.25,-2.25) 48(-4.25,-2.75)
  silkscreen extent -3.52,-3.52 3.53,3.52, body extent -4.5,-4.5 4.5,4.5, height 1.6
ICC_LQFP64_10X10_P050_SOCKET_YAMAICHI_IC149-064-069-B5_NM [mm]
  rect 1x2.5 smd rot 45 mask+0.05: 0(-6,-6) 0(6,6)
  rect 1x2.5 smd rot 135 mask+0.05: 0(-6,6) 0(6,-6)
  round 0.5 hole 1 unplated mask+0.05: 0(0,-3.1) 0(0,3.1)
  rect 0.3x1.7 smd mask+0.05: 1(-3.75,-5.9) 2(-3.25,-5.9) 3(-2.75,-5.9) 4(-2.25,-5.9) 5(-1.75,-5.9) 6(-1.25,-5.9) 7(-0.75,-5.9) 8(-0.25,-5.9) 9(0.25,-5.9) 10(0.75,-5.9) 11(1.25,-5.9) 12(1.75,-5.9) 13(2.25,-5.9) 14(2.75,-5.9) 15(3.25,-5.9) 16(3.75,-5.9) 33(3.75,5.9) 34(3.25,5.9) 35(2.75,5.9) 36(2.25,5.9) 37(1.75,5.9) 38(1.25,5.9) 39(0.75,5.9) 40(0.25,5.9) 41(-0.25,5.9) 42(-0.75,5.9) 43(-1.25,5.9) 44(-1.75,5.9) 45(-2.25,5.9) 46(-2.75,5.9) 47(-3.25,5.9) 48(-3.75,5.9)
  rect 1.7x0.3 smd mask+0.05: 17(5.9,-3.75) 18(5.9,-3.25) 19(5.9,-2.75) 20(5.9,-2.25) 21(5.9,-1.75) 22(5.9,-1.25) 23(5.9,-0.75) 24(5.9,-0.25) 25(5.9,0.25) 26(5.9,0.75) 27(5.9,1.25) 28(5.9,1.75) 29(5.9,2.25) 30(5.9,2.75) 31(5.9,3.25) 32(5.9,3.75) 49(-5.9,3.75) 50(-5.9,3.25) 51(-5.9,2.75) 52(-5.9,2.25) 53(-5.9,1.75) 54(-5.9,1.25) 55(-5.9,0.75) 56(-5.9,0.25) 57(-5.9,-0.25) 58(-5.9,-0.75) 59(-5.9,-1.25) 60(-5.9,-1.75) 61(-5.9,-2.25) 62(-5.9,-2.75) 63(-5.9,-3.25) 64(-5.9,-3.75)
  silkscreen extent -5.05,-5.05 5.05,5.05, body extent -6,-6 6,6, height 1.6
ICC_SO8_5X4_P127 [mm]
  rect 0.7x1.75 smd mask+0.05: 1(-1.905,-2.375) 2(-0.635,-2.375) 3(0.635,-2.375) 4(1.905,-2.375) 5(1.905,2.375) 6(0.635,2.375) 7(-0.635,2.375) 8(-1.905,2.375)
  silkscreen extent -2.72,-3.25 2.57,2, body extent -2.57,-3 2.57,3, height 1.75
ICC_WLCSP12_1P858x1P318_P040 [mm] "MCD-03166"
  round 0.215 smd paste+0 mask+0.04: A1(-0.6,0.4) A2(-0.2,0.4) A3(0.2,0.4) A4(0.6,0.4) B1(-0.6,0) B2(-0.2,0) B3(0.2,0) B4(0.6,0) C1(-0.6,-0.4) C2(-0.2,-0.4) C3(0.2,-0.4) C4(0.6,-0.4)
  silkscreen extent -1.07,-0.66 0.93,0.8, body extent -0.93,-0.66 0.93,0.66, height 0.62
"LED_0402_EVERLIGHT_16-213SYGC/S530-E3-TR8 _YELLOW-GREEN_1A2K_H0P45" [mm] "MCD-02330"
  rect 0.6x0.7 smd mask+0.05: 1(0.55,0) 2(-0.55,0)
  silkscreen extent -0.97,-0.3 0.13,0.3, body extent -0.55,-0.3 0.55,0.3, height 0.55
LED_0402_KINGBRIGHT_KPHHS-1005QBC-D-V_BLUE_1A2K_H0P5 [mm] "MCD-00706"
  rect 0.7x0.5 smd mask+0.05: 1(-0.55,0) 2(0.55,0)
  silkscreen extent -0.5,-0.38 1,0.38, body extent -0.5,-0.3 0.51,0.3, height 0.6
LED_0402_KINGBRIGHT_KPHHS-1005SURCK_HYPER-RED_1A2K_H0P5 [mm] "MCD-00708"
  rect 0.7x0.5 smd mask+0.05: 1(-0.55,0) 2(0.55,0)
  silkscreen extent -0.5,-0.38 1,0.38, body extent -0.5,-0.3 0.51,0.3, height 0.6
LED_BI-GR_WE-150141SV73110 [mm] "MCD-02631"
  rect 1.1x1.5 smd mask+0.05: 1(-0.75,1.5) 2(0.75,1.5) 3(-0.75,-1.5) 4(0.75,-1.5)
  silkscreen extent -1.65,-1.85 1.5,1.7, body extent -1.5,-1.85 1.5,1.85, height 2.1
MIRE_PLACE_SMD_0P8MM [mm]
  round 0.8 smd paste-10 mask+0.2: 1(0,0)
  Top Layer keep-out circle w0.01: c0,0 r0.804
MOS_SOT23 [mm]
  rect 1x1.4 smd mask+0.05: 1(-0.95,-1.1) 2(0.95,-1.1) 3(0,1.1)
  silkscreen extent -1.63,-0.82 1.63,0.82, body extent -1.56,-1.25 1.56,1.25, height 1.1
MOS_SOT23-5L [mm]
  rect 0.6x1.3 smd mask+0.05: 1(-0.95,-1.1) 2(0,-1.1) 3(0.95,-1.1) 4(0.95,1.1) 5(-0.95,1.1)
  silkscreen extent -1.6,-0.95 1.6,0.97, body extent -1.52,-1.25 1.52,1.25, height 1.45
NPN_SOT23 [mm]
  rect 1x1.4 smd mask+0.05: 1(-0.95,-1.1) 2(0.95,-1.1) 3(0,1.1)
  silkscreen extent -1.63,-0.82 1.63,0.82, body extent -1.56,-1.25 1.56,1.25, height 1.1
R0402 [mm]
  rect 0.51x0.7 smd mask+0.05: 1(-0.45,0) 2(0.45,0)
  body extent -0.52,-0.3 0.52,0.3, height 0.4
R0603 [mm]
  rect 0.64x1 smd mask+0.05: 1(-0.7,0) 2(0.7,0)
  silkscreen extent -1.05,-0.58 1.05,0.58, body extent -0.9,-0.5 0.9,0.5, height 0.56
REG_SOT23-5L [mm]
  rect 0.6x1.3 smd mask+0.05: 1(-0.95,-1.1) 2(0,-1.1) 3(0.95,-1.1) 4(0.95,1.1) 5(-0.95,1.1)
  silkscreen extent -1.6,-0.95 1.6,0.97, body extent -1.52,-1.25 1.52,1.25, height 1.1
REG_SOT223-TAB [mm]
  rect 1.5x1.65 smd mask+0.05: 1(-2.3,-3.175) 2(0,-3.175) 3(2.3,-3.175)
  rect 3.5x1.65 smd mask+0.05: 4(0,3.175)
  silkscreen extent -3.35,-2.15 3.35,2.12, body extent -3.35,-3.48 3.35,3.48, height 1.8
SOLDER-BRIDGE_R0603-0R [mil]
  round 10 smd paste-393.7: 1(-19.68,0) 2(23.62,0)
  Top Layer region: -5.91,19.68 13.78,0 -5.91,-19.69 47.24,-19.69 47.24,19.68 -5.91,19.68
  Top Layer region: -47.24,-19.69 -47.24,19.68 -15.75,19.68 3.94,0 -15.75,-19.69 -47.24,-19.69
  silkscreen extent -50,-23 50,23, body extent -36,-20 36,20, height 22
STICKER_BOARD_25X9 [mm] "Sticker to mention board CPN code"
  silkscreen extent -12.5,-4.5 12.5,4.5
STICKER_PRODUCT_25X9 [mm] "Sticker to mention board CPN code"
  silkscreen extent -12.5,-4.5 12.5,4.5
SWI_C&K_KSC321JLFS_BLACK [mm] "MCD-01799"
  rect 3.1x1 smd mask+0.05: 1(-2.8,2) 2(2.8,2) 3(-2.8,-2) 4(2.8,-2)
  silkscreen extent -3.25,-3.25 3.25,3.25, body extent -3.4,-3.25 3.4,3.25, height 3.5
SWI_C&K_KSC721JLFS_BLUE [mm] "MCD-01800"
  rect 3.1x1 smd mask+0.05: 1(-2.8,2) 2(2.8,2) 3(-2.8,-2) 4(2.8,-2)
  silkscreen extent -3.25,-3.25 3.25,3.25, body extent -3.4,-3.25 3.4,3.25, height 4.3
SWI_C&K_Y78B23110FP__ITT_KMR231GLFS [mm] "MCD-00715"
  rect 0.9x1 smd mask+0.05: 1(2.05,0.8) 2(2.05,-0.8) 3(-2.05,0.8) 4(-2.05,-0.8)
  rect 1.7x0.8 smd mask+0.05: 5(0,1.2)
  silkscreen extent -2.05,-1.43 2.05,1.43, body extent -2.3,-1.5 2.3,1.5, height 2.1
TP_SMD_0-6MM [mm]
  round 0.6 smd paste-10 mask+0.05: 1(0,0)
  silkscreen extent -0.5,-0.5 0.5,0.5
TP_SMD_1MM [mm]
  round 1 smd paste-10 mask+0.05: 1(0,0)
  silkscreen extent -0.7,-0.7 0.7,0.7

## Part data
B1: library part MCD-01800, "Switch tactile, SPST-NO, 32V, 50mA, 6.2x6.2mm", Manufacturer=C&K, Manufacturer_HQ_COO=Unknown, Manufacturer_Part_Number=KSC721JLFS, Package=6.2x6.2mm
B2: library part MCD-01799, "Switch tactile, SPST-NO, 32V, 50mA, 6.2x6.2mm", Manufacturer=C&K, Manufacturer_HQ_COO=Unknown, Manufacturer_Part_Number=KSC321JLFS, Package=6.2x6.2mm
B3: library part MCD-01485, "Switch tactile, SPST-NO, 32V, 50mA, 2.8x4.6mm", Manufacturer=C&K, Manufacturer_HQ_COO=Unknown, Manufacturer_Part_Number=KMR231GLFS, Package=2.8x4.6mm
C1 C2 C3 C4 C5 C12 C16 C17 C19 C20 C21 C25 C26 C27 C29 C30 C36 C38 C41: library part MCD-00006, "Capacitor, MLCC, 100nF, 16V, X7R, +/-10%, 0402, T=0.5mm", Manufacturer=YAGEO, Manufacturer_Part_Number=CC0402KRX7R7BB104, Package=0402
C6 C40: library part MCD-00205, "Capacitor, MLCC, 100pF, 50V, NPO, +/-5%, 0402, T=0.5mm", Manufacturer=YAGEO, Manufacturer_Part_Number=CC0402JRNPO9BN101, Package=0402
C7 C39: library part MCD-01099, "Capacitor, MLCC, 100nF, 50V, X7R, +/-10%, 0603, T=0.8mm", Manufacturer=YAGEO, Manufacturer_Part_Number=CC0603KRX7R9BB104, Package=0603
C8 C9: library part MCD-00015, "Capacitor, MLCC, 10pF, 50V, NPO, +/-5%, 0402, T=0.5mm", Manufacturer=YAGEO, Manufacturer_Part_Number=CC0402JRNPO9BN100, Package=0402
C10: library part MCD-00016, "Capacitor, MLCC, 20pF, 50V, NPO, +/- 5%, 0402, T=0.5mm", Manufacturer=YAGEO, Manufacturer_Part_Number=CC0402JRNPO9BN200, Package=0402
C11 C42: library part MCD-00099, "Capacitor, MLCC, 10uF, 10V, X5R, +/-10%, 0603, T=0.8mm", Manufacturer=MURATA, Manufacturer_Part_Number=GRM188R61A106KE69D, Package=0603
C13: library part MCD-02198, "Capacitor, MLCC, 10nF, 50V, X7R, +/-10%, 0402, T=0.5mm", Manufacturer=YAGEO, Manufacturer_Part_Number=CC0402KRX7R9BB103, Package=0402
C14 C15 C18 C23 C31 C37: library part MCD-00010, "Capacitor, MLCC, 1uF, 16V, X5R, +/-10%, 0603, T=0.8mm", Manufacturer=YAGEO, Manufacturer_Part_Number=CC0603KRX5R7BB105, Package=0603
C22 C24: library part MCD-00014, "Capacitor, MLCC, 10uF, 25V, X5R, +/-10%, 0805, T=0.85mm", Manufacturer=YAGEO, Manufacturer_Part_Number=CC0805KRX5R8BB106, Package=0805
C28 C43: library part MCD-01721, "Capacitor, MLCC, 4.7uF, 10V, X5R, +/-10%, 0603, T=0.8mm", Manufacturer=YAGEO, Manufacturer_Part_Number=CC0603KRX5R6BB475, Package=0603
C32 C35: library part MCD-03185, "Capacitor, MLCC, 6pF, 50V, NPO, +/-0,25pF, 0402, T=0.5mm", Manufacturer=MURATA, Manufacturer_Part_Number=GJM1555C1H6R0CB01, Package=0402
C33 C34: library part MCD-04081, "Capacitor, MLCC, 7.5pF, 50V, NP0/C0G, +/-0.1pF, 0402, T=0.5mm", Manufacturer=MURATA, Manufacturer_Part_Number=GJM1555C1H7R5BB01D, Package=0402
CN1 CN13: library part MCD-03232, "USB_TypeC, 24 pins, RA, SMD, T=2.96mm", Manufacturer="AMPHENOL CS", Manufacturer_Part_Number=12401826E412A
CN2 CN3: library part MCD-00214, "Header, 2x1, 2.54mm, VR, TH, T=5.84mm/10.16mm", Manufacturer=SAMTEC, Manufacturer_Part_Number=TSW-102-09-G-S
CN4: library part MCD-01226, "Header, 5x2, 1.27mm, VR, SMD, T=7.02mm", Manufacturer=SAMTEC, Manufacturer_Part_Number=FTSH-105-01-L-DV-K
CN5: library part MCD-02080, "Socket, 10x1, 2.54mm, VR, TH, T=8.51/2.64mm", Manufacturer=SAMTEC, Manufacturer_Part_Number=SSW-110-01-G-S
CN6 CN9: library part MCD-01743, "Socket, 8x1, 2.54mm, VR, TH, T=8.51/2.64mm", Manufacturer=SAMTEC, Manufacturer_Part_Number=SSW-108-01-G-S
CN7 CN10: library part MCD-00213, "Header, 19x2, 2.54mm, VR, TH, T=5.84mm/10.16mm", Manufacturer=SAMTEC, Manufacturer_Part_Number=TSW-119-09-G-D
CN8: library part MCD-02079, "Socket, 6x1, 2.54mm, VR, TH, T=8.51/2.64mm", Manufacturer=SAMTEC, Manufacturer_Part_Number=SSW-106-01-G-S
CN11: library part MCD-00029, "Header, 4x1, 2.54mm, VR, TH, T=5.84mm/2.54mm", Manufacturer=SAMTEC, Manufacturer_Part_Number=TSW-104-07-G-S
CN12 JP2 JP4 JP5 JP6 JP7 JP8: library part MCD-00683, "Header, 2x1, 2.54mm, VR, TH, T=5.84mm/2.54mm", Manufacturer=SAMTEC, Manufacturer_Part_Number=TSW-102-07-G-S
CN14: library part MCD-04055, "Header, 3x1, 2.5mm, RA, TH, T=8.1mm/3.5mm", Manufacturer="WURTH ELEKTRONIK", Manufacturer_Part_Number=691382010003
D1 D2: library part MCD-00034, "Diode, Schottky, 0V53, 1A, 10V, SOD323", Manufacturer=STMICROELECTRONICS, Manufacturer_HQ_COO=EU, Package=SOD323
HW1: library part MCD-00547, "Sticker product, 25x9mm", Manufacturer=N/A, Manufacturer_HQ_COO=Unknown
HW2: library part MCD-00235, "Sticker Board, 25x9mm", Manufacturer=N/A
HW9 HW10 HW16 HW17: library part MCD-03135, "Fiducial Pad, 0.8mm", Manufacturer=N/A, Manufacturer_HQ_COO=Unknown
JP1: library part MCD-00686, "Header, 4x2, 2.54mm, VR, TH, T=5.84mm/2.54mm", Manufacturer=SAMTEC, Manufacturer_Part_Number=TSW-104-07-G-D
JP3 JP9: library part MCD-00045, "Header, 2x1, 2.54mm, VR, TH, T=5.84mm/2.54mm", Manufacturer=SAMTEC, Manufacturer_Part_Number=TSW-102-07-G-S
LD1 LD3: library part MCD-02330, "LED Bicolor, Yellow/Green, 2V, 25mA, 0402", Manufacturer=EVERLIGHT, Manufacturer_Part_Number=16-213SYGC/S530-E3/TR8, Package=0402
LD2: library part MCD-00706, "LED, Blue, 3V3, 20mA, 0402", Manufacturer=KINGBRIGHT, Manufacturer_Part_Number=KPHHS-1005QBC-D-V, Package=0402
LD4: library part MCD-02631, "LED Bicolor, Red/Green, 2V, 20mA, 4-PLCC", Manufacturer="WURTH ELEKTRONIK", Manufacturer_Part_Number=150141SV73110, Package=4-PLCC
LD5: library part MCD-00708, "LED, Red, 1V95, 20mA, 0402", Manufacturer=KINGBRIGHT, Manufacturer_Part_Number=KPHHS-1005SURCK, Package=0402
R1 R2 R8: library part MCD-00059, "Resistor, 100K, 0402, +/-1%, 1/16W", Manufacturer=YAGEO, Manufacturer_Part_Number=RC0402FR-07100KL, Package=0402
R3: library part MCD-00069, "Resistor, 36K, 0402, +/-1%, 1/16W", Manufacturer=YAGEO, Manufacturer_Part_Number=RC0402FR-0736KL, Package=0402
R4: library part MCD-00068, "Resistor, 1K5, 0402, +/-1%, 1/16W", Manufacturer=YAGEO, Manufacturer_Part_Number=RC0402FR-071K5L, Package=0402
R5 R7 R13 R18 R24 R25 R32 R48: library part MCD-00053, "Resistor, 10K, 0402, +/-1%, 1/16W", Manufacturer=YAGEO, Manufacturer_Part_Number=RC0402FR-0710KL, Package=0402
R6 R14 R23 R41: library part MCD-00067, "Resistor, 100R, 0402, +/- 1%, 1/16W", Manufacturer=YAGEO, Manufacturer_Part_Number=RC0402FR-07100RL, Package=0402
R9 R17 R19 R34 R45 R47: library part MCD-00333, "Resistor, 5K1, 0402, +/-1%, 1/16W", Manufacturer=YAGEO, Manufacturer_Part_Number=RC0402FR-075K1L, Package=0402
R10 R12 R33: library part MCD-00061, "Resistor, 1K, 0402, +/-1%,1/16W", Manufacturer=YAGEO, Manufacturer_Part_Number=RC0402FR-071KL, Package=0402
R11: library part MCD-00062, "Resistor, 330R, 0402, +/-1%, 1/16W", Manufacturer=YAGEO, Manufacturer_Part_Number=RC0402FR-07330RL, Package=0402
R15 R31: library part MCD-00507, "Resistor, 680R, 0402, +/-1%, 1/16W", Manufacturer=YAGEO, Manufacturer_Part_Number=RC0402FR-07680RL, Package=0402
R16: library part MCD-00461, "Resistor, 360R, 0402, +/-1%, 1/16W", Manufacturer=YAGEO, Manufacturer_Part_Number=RC0402FR-07360RL, Package=0402
R20 R44: library part MCD-00513, "Resistor, 680K, 0402, +/-1%, 1/16W", Manufacturer=YAGEO, Manufacturer_Part_Number=RC0402FR-07680KL, Package=0402
R21 R43: library part MCD-00413, "Resistor, 180K, 0402, +/-1%, 1/16W", Manufacturer=YAGEO, Manufacturer_Part_Number=RC0402FR-07180KL, Package=0402
R22 R27 R35 R36 R37 R38: library part MCD-00052, "Resistor, 0R, 0402, +/-5%, 1/16W", Manufacturer=YAGEO, Manufacturer_Part_Number=RC0402JR-070RL, Package=0402
R26: library part MCD-00455, "Resistor, 33R, 0402, +/-1%, 1/16W", Manufacturer=YAGEO, Manufacturer_Part_Number=RC0402FR-0733RL, Package=0402
R28: library part MCD-01943, "Resistor, 15K, 0402, +/-1%, 1/16W", Manufacturer=YAGEO, Manufacturer_Part_Number=RC0402FR-0715KL, Package=0402
R29: library part MCD-00182, "Resistor, 1M, 0402, +/-1%, 1/16W", Manufacturer=YAGEO, Manufacturer_Part_Number=RC0402FR-071ML, Package=0402
R30: library part MCD-00063, "Resistor, 47K, 0402, +/-1%, 1/16W", Manufacturer=YAGEO, Manufacturer_Part_Number=RC0402FR-0747KL, Package=0402
R39: library part MCD-00531, "Resistor, 82K, 0402, +/-1%, 1/16W", Manufacturer=YAGEO, Manufacturer_Part_Number=RC0402FR-0782KL, Package=0402
R40: library part MCD-00258, "Resistor, 33K, 0402, +/-1%, 1/16W", Manufacturer=YAGEO, Manufacturer_Part_Number=RC0402FR-0733KL, Package=0402
R42: library part MCD-00056, "Resistor, 0R, 0603, +/-5%, 1/10W", Manufacturer=YAGEO, Manufacturer_Part_Number=RC0603JR-070RL, Package=0603
R46: library part MCD-00194, "Resistor, 120R, 0402, +/-1%, 1/16W", Manufacturer=YAGEO, Manufacturer_Part_Number=RC0402FR-07120RL, Package=0402
SB1 SB2 SB3 SB4 SB5 SB6 SB7 SB8 SB9 SB10 SB11 SB12 SB13 SB14 SB15 SB16 SB17 SB18 SB19 SB20: library part MCD-00071, "Resistor, 0R, SB0603, 5%, 0.1W", Manufacturer=YAGEO, Manufacturer_HQ_COO=Unknown, Manufacturer_Part_Number=RC0603JR-070RL, Package=0603
T1: library part MCD-00073, "Transistor, NPN, 40V, 800mA, SOT23", Manufacturer="ON SEMICONDUCTOR", Manufacturer_Part_Number=BSR14, Package=SOT23
T2: library part MCD-01969, "Transistor, MOSFET, N-CH, 60V, 265mA, SOT23-3", Manufacturer=NEXPERIA, Manufacturer_Part_Number=BSN20BK, Package=SOT23-3
TP1 TP2 TP3 TP5: library part MCD-00074, "Test Point, SMD, 1mm", Manufacturer=N/A, Manufacturer_HQ_COO=Unknown
TP4: library part MCD-00631, "Test Point, SMD, 0.6mm", Manufacturer=N/A, Manufacturer_HQ_COO=Unknown
U1: library part MCD-00083, "Power Switch, Enhanced single channel", Manufacturer=STMICROELECTRONICS, Manufacturer_HQ_COO=EU, Package=SOT23-5
U2 U19: library part MCD-01207, "Diode, ESD TVS, 22V, 200nA, 25V8, QFN1610", Manufacturer=STMICROELECTRONICS, Manufacturer_HQ_COO=EU, Manufacturer_Part_Number=ESDA25P35-1U1M, Package=QFN1610
U3: library part MCD-03850, "MCU, ARM Cortex-M3 32-bit, 128KB Flash, 20KB RAM, No Crypto", Manufacturer=STMICROELECTRONICS, Manufacturer_Part_Number=STM32F103CBT6, Package=LQFP48
U4 U8: library part MCD-00136, "Diode, ESD Transil, 3V, 1uA, 7V2, SOT323-5", Manufacturer=STMICROELECTRONICS, Manufacturer_HQ_COO=EU, Package=SOT323-5
U5 U16: library part MCD-00163, "Diode, ESD protection, 5V25, 150nA, 6V, SOT23-6", Manufacturer=STMICROELECTRONICS, Package=SOT23-6
U6: library part MCD-03166, "Power switch, 28V/5A OVP with Low On-resistance, Integrated TVS", Manufacturer="ON SEMICONDUCTOR", Package=WLCSP-12
U7: library part MCD-00663, "LDO, 3V3, 200mA, Low quiescent current, Very low noise", Manufacturer=STMICROELECTRONICS, Manufacturer_HQ_COO=EU, Package=SOT23-5
U9: library part MCD-03339, "LDO, 1V5 to 5V5V, 1A adjustable", Manufacturer=STMICROELECTRONICS, Package="DFN6 3x3mm"
U10: library part MCD-00088, "LDO, Adjustable and fixed low drop positive voltage regulator", Manufacturer=STMICROELECTRONICS, Manufacturer_HQ_COO=EU, Package=SOT223-4
U11 U12 U13: library part MCD-00170, "Diode, ESD TVS, 3V, 100nA, 8V, ST0201", Manufacturer=STMICROELECTRONICS, Manufacturer_HQ_COO=EU, Manufacturer_Part_Number=ESDALC6V1-1U2, Package=ST0201
U14: library part MCD-03542, "MCU, ARM Cortex-M0+ 32-bit, 128KB Flash, 18KB RAM", Manufacturer=STMICROELECTRONICS, Manufacturer_Part_Number=STM32C071RBT6, Package=LQFP64
U15: library part MCD-00129, "IC, High-Speed CAN flexible data rate transceiver", Manufacturer=MICROCHIP, Manufacturer_Part_Number=MCP2562FDT-H/SN, Package=SO-8
U17: library part MCD-03166, "Power switch, 28V/5A OVP with Low On-resistance, Integrated TVS", Manufacturer="ON SEMICONDUCTOR", Manufacturer_Part_Number=FPF3380UCX, Package=WLCSP-12
U18: library part MCD-01228, "Diode, ESD TVS, 24V, 10nA, 29V7, SOT323-3", Manufacturer=STMICROELECTRONICS, Manufacturer_HQ_COO=EU, Manufacturer_Part_Number=ESDCAN03-2BWY, Package=SOT323-3
X1: library part MCD-00092, "Crystal, 8MHz, 8pF, +/-20ppm, 500R, 3.2x2.5mm", Manufacturer=NDK, Manufacturer_Part_Number=NX3225GD-8MHZ-EXS00A-CG04874, Package=3.2x2.5mm
X2: library part MCD-01479, "Crystal, 32.768kHz, 6pF, +/-20ppm, 80K, 2.05x1.2mm", Manufacturer=NDK, Manufacturer_Part_Number=NX2012SA-32.768KHZ-EXS00A-MU00527, Package=2.05x1.2mm
X3: library part MCD-02262, "Crystal, 48MHz, 7pF, +/-20 ppm, 80R, 1.6x1.2mm", Manufacturer=NDK, Manufacturer_Part_Number=NX1612SA-48MHZ-EXS00A-CS13734, Package=1.6x1.2mm

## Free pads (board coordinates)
  round 3.2 on Mech2: 0(10.871,52.578) 0(43.891,0.508) 0(59.131,51.308)
  oval 0.8x1.4 on Top Paste mask+0.05: 0(14.881,0.508) 0(15.241,3.958) 0(23.501,3.958) 0(23.861,0.508) 0(38.4,77.958) 0(38.76,74.508) 0(47.02,74.508) 0(47.38,77.958)
  round 0.508 on Mech16: 1(11.399,-30.898) 1(60.247,-30.898)
  round 3.2 hole 3.2 unplated: H1(59.131,51.308) H2(10.871,52.578) H3(43.891,0.508)

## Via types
v1: diameter 0.45, hole 0.25, Top Layer to Bottom Layer, tented both sides, 830 vias
v2: diameter 0.7, hole 0.4, Top Layer to Bottom Layer, tented both sides, 21 vias
v3: diameter 0.5, hole 0.3, Top Layer to Bottom Layer, tented both sides, 11 vias

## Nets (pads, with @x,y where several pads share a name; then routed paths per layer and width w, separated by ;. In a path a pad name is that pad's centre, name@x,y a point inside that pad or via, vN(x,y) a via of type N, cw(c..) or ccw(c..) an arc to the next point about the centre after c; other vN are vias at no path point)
3V3: B3.2 B3.4 C38.1 CN4.3 CN6.2 CN6.4 CN7.12 CN7.16 JP5.2 JP8.1 R15.2 R16.2 R34.2 SB2.2 U8.4 U15.5 | length 200.5
  Top Layer w0.3: B3.2@14.805,51.733 B3.4@18.905,51.733 v1(20.817,51.733) ; SB2.2@51.335,55.738 v1(51.335,56.718) ; R15.2@51.78,70.433 R16.2@54.305,70.433 54.532,70.433 55.055,69.91 v1(55.055,65.67)
  Top Layer w0.4: CN4.3@2.672,66.547 3.886,66.547 4.377,66.055 v1(4.705,66.055) ; v1(10.848,60.115) U8.4@11.532,60.115 12.527,60.115 13.714,58.928 JP8.1@15.316,58.928 ; v1(12.037,21.768) 12.662,22.393 R34.2@15.99,22.393 ; v1@37.671,12.258 C38.1@38.326,12.258 U15.5@38.326,10.712
  Top Layer w0.5: CN7.16@5.791,30.988 CN6.4@10.871,30.988 ; CN7.12@5.791,36.068 CN6.2@10.871,36.068 ; v2@9.36,45.237 v2(20.8,45.237) 26.317,45.237 28.513,47.433 v3(48.172,47.433) 48.833,47.433 51.76,50.36 JP5.2@51.76,53.208 51.76,55.2 51.41,55.55 51.275,55.55
  Bottom Layer w0.25: CN6.4@10.871,30.988 9.2,29.317 9.2,22.768 9.878,22.09 11.715,22.09 v1(12.037,21.768)
  Bottom Layer w0.3: v1(51.335,56.718) 51.335,59.477 55.055,63.197 v1(55.055,65.67)
  Bottom Layer w0.4: v1(4.705,66.055) 9.82,66.055 10.848,65.028 v1(10.848,60.115) ; v1(37.67,12.257) 47.435,12.257 48.733,13.555 48.733,29.337 48.172,29.897 v3(48.172,47.433)
  Bottom Layer w0.5: v2@9.36,45.237 9.29,45.167 9.29,37.649 CN6.2@10.871,36.068 9.29,34.487 9.29,32.569 CN6.4@10.871,30.988 ; JP8.1@15.316,58.928 20.813,53.432 20.8,53.419 v2(20.8,45.237)
  other v2: 9.36,45.187
3V3_STLK: C2.1 C3.1 C5.1 C14.2 C16.2 C19.1 CN11.1 LD4.4 T1.3 U3.1 U3.9 U3.24 U3.36 U3.48 U7.5 | length 81.8
  Top Layer w0.3: v2(29.955,72.817) 29.955,75.835 31.539,77.419 T1.3@35.027,77.419 v1(37.006,77.419) ; v1(49.328,78.76) 49.915,79.347 57.241,79.347 LD4.4@58.63,77.958
  Top Layer w0.35: 27.44,72.82 CN11.1@27.44,78.108 ; U3.9@27.678,65.482 28.95,65.482 29.442,65.975 29.442,68.583 28.543,69.482 U3.1@27.678,69.482 ; U3.48@29.178,70.982 C2.1@29.178,72.82 ; v3(34.412,69.247) 35.462,70.297 C5.1@37.38,70.297 37.38,69.718 37.145,69.482 U3.36@36.178,69.482
  Top Layer w0.5: C3.1@25.371,72.82 27.44,72.82 ; U3.1@27.654,69.559 27.44,69.772 27.44,72.82 ; C2.1@29.178,72.82 27.44,72.82 ; C2.1@29.181,72.817 v2(29.955,72.817) ; C19.1@34.742,60.65 C19.1@34.783,60.65 ; C19.1@34.783,60.648 C19.1@34.783,60.65 ; v2(34.783,63.75) C19.1@34.783,60.65 ; U7.5@40.199,60.65 C16.2@38.911,60.65 C14.2@37.71,60.65 C19.1@34.783,60.65
  Bottom Layer w0.3: v1(37.006,77.419) 37.593,76.833 48.028,76.833 49.328,78.132 v1(49.328,78.76)
  Bottom Layer w0.5: v2(29.955,72.817) 30.843,72.817 34.4,69.26 34.4,64.133 v2(34.783,63.75)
